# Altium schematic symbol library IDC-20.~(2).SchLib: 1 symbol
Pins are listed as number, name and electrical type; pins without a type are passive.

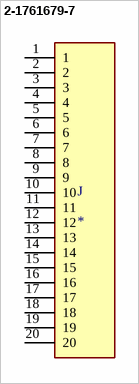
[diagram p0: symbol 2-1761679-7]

## 2-1761679-7
designator J
IDC LOW PRO HDR 20P VERT BLUE; MF: TE Connectivity; Product_Type: Connector; MP: 2-1761679-7; Centerline_Pitch: 2.54 mm[.1 in]; Number_of_Positions: 20
footprint TE_2-1761679-7
pins: 1, 2, 3, 4, 5, 6, 7, 8, 9, 10, 11, 12, 13, 14, 15, 16, 17, 18, 19, 20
